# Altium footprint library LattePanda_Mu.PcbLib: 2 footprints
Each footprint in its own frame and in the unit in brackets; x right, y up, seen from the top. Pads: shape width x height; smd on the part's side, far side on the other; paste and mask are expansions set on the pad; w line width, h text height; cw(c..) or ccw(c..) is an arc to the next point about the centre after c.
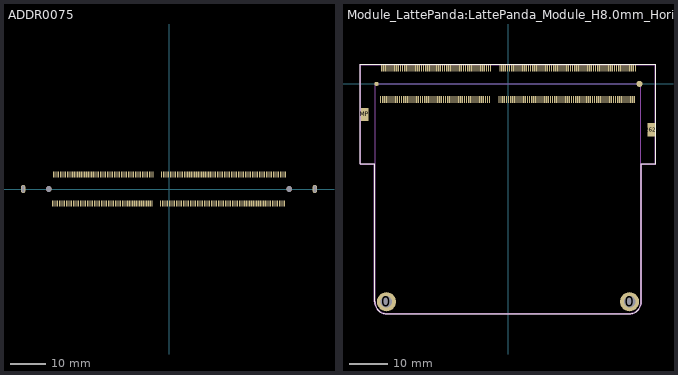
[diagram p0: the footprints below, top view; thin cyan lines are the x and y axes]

## ADDR0075 [mm]
pads (264):
  rect 0.3x1.75 smd paste+0 mask+0.05: 1(33.375,4.1) 2(33.125,-4.1) 3(32.875,4.1) 4(32.625,-4.1) 5(32.375,4.1) 6(32.125,-4.1) 7(31.875,4.1) 8(31.625,-4.1) 9(31.375,4.1) 10(31.125,-4.1) 11(30.875,4.1) 12(30.625,-4.1) 13(30.375,4.1) 14(30.125,-4.1) 15(29.875,4.1) 16(29.625,-4.1) 17(29.375,4.1) 18(29.125,-4.1) 19(28.875,4.1) 20(28.625,-4.1) 21(28.375,4.1) 22(28.125,-4.1) 23(27.875,4.1) 24(27.625,-4.1) 25(27.375,4.1) 26(27.125,-4.1) 27(26.875,4.1) 28(26.625,-4.1) 29(26.375,4.1) 30(26.125,-4.1) 31(25.875,4.1) 32(25.625,-4.1) 33(25.375,4.1) 34(25.125,-4.1) 35(24.875,4.1) 36(24.625,-4.1) 37(24.375,4.1) 38(24.125,-4.1) 39(23.875,4.1) 40(23.625,-4.1) 41(23.375,4.1) 42(23.125,-4.1) 43(22.875,4.1) 44(22.625,-4.1) 45(22.375,4.1) 46(22.125,-4.1) 47(21.875,4.1) 48(21.625,-4.1) 49(21.375,4.1) 50(21.125,-4.1) 51(20.875,4.1) 52(20.625,-4.1) 53(20.375,4.1) 54(20.125,-4.1) 55(19.875,4.1) 56(19.625,-4.1) 57(19.375,4.1) 58(19.125,-4.1) 59(18.875,4.1) 60(18.625,-4.1) 61(18.375,4.1) 62(18.125,-4.1) 63(17.875,4.1) 64(17.625,-4.1) 65(17.375,4.1) 66(17.125,-4.1) 67(16.875,4.1) 68(16.625,-4.1) 69(16.375,4.1) 70(16.125,-4.1) 71(15.875,4.1) 72(15.625,-4.1) 73(15.375,4.1) 74(15.125,-4.1) 75(14.875,4.1) 76(14.625,-4.1) 77(14.375,4.1) 78(14.125,-4.1) 79(13.875,4.1) 80(13.625,-4.1) 81(13.375,4.1) 82(13.125,-4.1) 83(12.875,4.1) 84(12.625,-4.1) 85(12.375,4.1) 86(12.125,-4.1) 87(11.875,4.1) 88(11.625,-4.1) 89(11.375,4.1) 90(11.125,-4.1) 91(10.875,4.1) 92(10.625,-4.1) 93(10.375,4.1) 94(10.125,-4.1) 95(9.875,4.1) 96(9.625,-4.1) 97(9.375,4.1) 98(9.125,-4.1) 99(8.875,4.1) 100(8.625,-4.1) 101(8.375,4.1) 102(8.125,-4.1) 103(7.875,4.1) 104(7.625,-4.1) 105(7.375,4.1) 106(7.125,-4.1) 107(6.875,4.1) 108(6.625,-4.1) 109(6.375,4.1) 110(6.125,-4.1) 111(5.875,4.1) 112(5.625,-4.1) 113(5.375,4.1) 114(5.125,-4.1) 115(4.875,4.1) 116(4.625,-4.1) 117(4.375,4.1) 118(4.125,-4.1) 119(3.875,4.1) 120(3.625,-4.1) 121(3.375,4.1) 122(3.125,-4.1) 123(2.875,4.1) 124(2.625,-4.1) 125(2.375,4.1) 126(2.125,-4.1) 127(1.875,4.1) 128(1.625,-4.1) 129(1.375,4.1) 130(1.125,-4.1) 131(0.875,4.1) 132(0.625,-4.1) 133(0.375,4.1) 134(0.125,-4.1) 135(-0.125,4.1) 136(-0.375,-4.1) 137(-0.625,4.1) 138(-0.875,-4.1) 139(-1.125,4.1) 140(-1.375,-4.1) 141(-1.625,4.1) 142(-1.875,-4.1) 143(-2.125,4.1) 144(-2.375,-4.1) 145(-4.625,4.1) 146(-4.875,-4.1) 147(-5.125,4.1) 148(-5.375,-4.1) 149(-5.625,4.1) 150(-5.875,-4.1) 151(-6.125,4.1) 152(-6.375,-4.1) 153(-6.625,4.1) 154(-6.875,-4.1) 155(-7.125,4.1) 156(-7.375,-4.1) 157(-7.625,4.1) 158(-7.875,-4.1) 159(-8.125,4.1) 160(-8.375,-4.1) 161(-8.625,4.1) 162(-8.875,-4.1) 163(-9.125,4.1) 164(-9.375,-4.1) 165(-9.625,4.1) 166(-9.875,-4.1) 167(-10.125,4.1) 168(-10.375,-4.1) 169(-10.625,4.1) 170(-10.875,-4.1) 171(-11.125,4.1) 172(-11.375,-4.1) 173(-11.625,4.1) 174(-11.875,-4.1) 175(-12.125,4.1) 176(-12.375,-4.1) 177(-12.625,4.1) 178(-12.875,-4.1) 179(-13.125,4.1) 180(-13.375,-4.1) 181(-13.625,4.1) 182(-13.875,-4.1) 183(-14.125,4.1) 184(-14.375,-4.1) 185(-14.625,4.1) 186(-14.875,-4.1) 187(-15.125,4.1) 188(-15.375,-4.1) 189(-15.625,4.1) 190(-15.875,-4.1) 191(-16.125,4.1) 192(-16.375,-4.1) 193(-16.625,4.1) 194(-16.875,-4.1) 195(-17.125,4.1) 196(-17.375,-4.1) 197(-17.625,4.1) 198(-17.875,-4.1) 199(-18.125,4.1) 200(-18.375,-4.1) 201(-18.625,4.1) 202(-18.875,-4.1) 203(-19.125,4.1) 204(-19.375,-4.1) 205(-19.625,4.1) 206(-19.875,-4.1) 207(-20.125,4.1) 208(-20.375,-4.1) 209(-20.625,4.1) 210(-20.875,-4.1) 211(-21.125,4.1) 212(-21.375,-4.1) 213(-21.625,4.1) 214(-21.875,-4.1) 215(-22.125,4.1) 216(-22.375,-4.1) 217(-22.625,4.1) 218(-22.875,-4.1) 219(-23.125,4.1) 220(-23.375,-4.1) 221(-23.625,4.1) 222(-23.875,-4.1) 223(-24.125,4.1) 224(-24.375,-4.1) 225(-24.625,4.1) 226(-24.875,-4.1) 227(-25.125,4.1) 228(-25.375,-4.1) 229(-25.625,4.1) 230(-25.875,-4.1) 231(-26.125,4.1) 232(-26.375,-4.1) 233(-26.625,4.1) 234(-26.875,-4.1) 235(-27.125,4.1) 236(-27.375,-4.1) 237(-27.625,4.1) 238(-27.875,-4.1) 239(-28.125,4.1) 240(-28.375,-4.1) 241(-28.625,4.1) 242(-28.875,-4.1) 243(-29.125,4.1) 244(-29.375,-4.1) 245(-29.625,4.1) 246(-29.875,-4.1) 247(-30.125,4.1) 248(-30.375,-4.1) 249(-30.625,4.1) 250(-30.875,-4.1) 251(-31.125,4.1) 252(-31.375,-4.1) 253(-31.625,4.1) 254(-31.875,-4.1) 255(-32.125,4.1) 256(-32.375,-4.1) 257(-32.625,4.1) 258(-32.875,-4.1) 259(-33.125,4.1) 260(-33.375,-4.1)
  oval 1.2x2.4 hole 0.7 slot 1.9 at 90 deg paste-2539.97: 261(-41.75,0) 261(41.75,0)
  round 1.6 hole 1.6 unplated paste-2539.97: 261(-34.4,0) 261(34.4,0)
3D body "2.STEP": height 28.6, standoff -1, extent -4.857,-42.499 80.443,-34.099

## Module_LattePanda:LattePanda_Module_H8.0mm_Horizontal [mm]
pads (266):
  round 5 hole 3 mask+0.05: 0(-31.8,-57) 0(31.8,-57)
  rect 0.3x1.75 smd paste+0: 1(33.375,4.1) 2(33.125,-4.1) 3(32.875,4.1) 4(32.625,-4.1) 5(32.375,4.1) 6(32.125,-4.1) 7(31.875,4.1) 8(31.625,-4.1) 9(31.375,4.1) 10(31.125,-4.1) 11(30.875,4.1) 12(30.625,-4.1) 13(30.375,4.1) 14(30.125,-4.1) 15(29.875,4.1) 16(29.625,-4.1) 17(29.375,4.1) 18(29.125,-4.1) 19(28.875,4.1) 20(28.625,-4.1) 21(28.375,4.1) 22(28.125,-4.1) 23(27.875,4.1) 24(27.625,-4.1) 25(27.375,4.1) 26(27.125,-4.1) 27(26.875,4.1) 28(26.625,-4.1) 29(26.375,4.1) 30(26.125,-4.1) 31(25.875,4.1) 32(25.625,-4.1) 33(25.375,4.1) 34(25.125,-4.1) 35(24.875,4.1) 36(24.625,-4.1) 37(24.375,4.1) 38(24.125,-4.1) 39(23.875,4.1) 40(23.625,-4.1) 41(23.375,4.1) 42(23.125,-4.1) 43(22.875,4.1) 44(22.625,-4.1) 45(22.375,4.1) 46(22.125,-4.1) 47(21.875,4.1) 48(21.625,-4.1) 49(21.375,4.1) 50(21.125,-4.1) 51(20.875,4.1) 52(20.625,-4.1) 53(20.375,4.1) 54(20.125,-4.1) 55(19.875,4.1) 56(19.625,-4.1) 57(19.375,4.1) 58(19.125,-4.1) 59(18.875,4.1) 60(18.625,-4.1) 61(18.375,4.1) 62(18.125,-4.1) 63(17.875,4.1) 64(17.625,-4.1) 65(17.375,4.1) 66(17.125,-4.1) 67(16.875,4.1) 68(16.625,-4.1) 69(16.375,4.1) 70(16.125,-4.1) 71(15.875,4.1) 72(15.625,-4.1) 73(15.375,4.1) 74(15.125,-4.1) 75(14.875,4.1) 76(14.625,-4.1) 77(14.375,4.1) 78(14.125,-4.1) 79(13.875,4.1) 80(13.625,-4.1) 81(13.375,4.1) 82(13.125,-4.1) 83(12.875,4.1) 84(12.625,-4.1) 85(12.375,4.1) 86(12.125,-4.1) 87(11.875,4.1) 88(11.625,-4.1) 89(11.375,4.1) 90(11.125,-4.1) 91(10.875,4.1) 92(10.625,-4.1) 93(10.375,4.1) 94(10.125,-4.1) 95(9.875,4.1) 96(9.625,-4.1) 97(9.375,4.1) 98(9.125,-4.1) 99(8.875,4.1) 100(8.625,-4.1) 101(8.375,4.1) 102(8.125,-4.1) 103(7.875,4.1) 104(7.625,-4.1) 105(7.375,4.1) 106(7.125,-4.1) 107(6.875,4.1) 108(6.625,-4.1) 109(6.375,4.1) 110(6.125,-4.1) 111(5.875,4.1) 112(5.625,-4.1) 113(5.375,4.1) 114(5.125,-4.1) 115(4.875,4.1) 116(4.625,-4.1) 117(4.375,4.1) 118(4.125,-4.1) 119(3.875,4.1) 120(3.625,-4.1) 121(3.375,4.1) 122(3.125,-4.1) 123(2.875,4.1) 124(2.625,-4.1) 125(2.375,4.1) 126(2.125,-4.1) 127(1.875,4.1) 128(1.625,-4.1) 129(1.375,4.1) 130(1.125,-4.1) 131(0.875,4.1) 132(0.625,-4.1) 133(0.375,4.1) 134(0.125,-4.1) 135(-0.125,4.1) 136(-0.375,-4.1) 137(-0.625,4.1) 138(-0.875,-4.1) 139(-1.125,4.1) 140(-1.375,-4.1) 141(-1.625,4.1) 142(-1.875,-4.1) 143(-2.125,4.1) 144(-2.375,-4.1) 145(-4.625,4.1) 146(-4.875,-4.1) 147(-5.125,4.1) 148(-5.375,-4.1) 149(-5.625,4.1) 150(-5.875,-4.1) 151(-6.125,4.1) 152(-6.375,-4.1) 153(-6.625,4.1) 154(-6.875,-4.1) 155(-7.125,4.1) 156(-7.375,-4.1) 157(-7.625,4.1) 158(-7.875,-4.1) 159(-8.125,4.1) 160(-8.375,-4.1) 161(-8.625,4.1) 162(-8.875,-4.1) 163(-9.125,4.1) 164(-9.375,-4.1) 165(-9.625,4.1) 166(-9.875,-4.1) 167(-10.125,4.1) 168(-10.375,-4.1) 169(-10.625,4.1) 170(-10.875,-4.1) 171(-11.125,4.1) 172(-11.375,-4.1) 173(-11.625,4.1) 174(-11.875,-4.1) 175(-12.125,4.1) 176(-12.375,-4.1) 177(-12.625,4.1) 178(-12.875,-4.1) 179(-13.125,4.1) 180(-13.375,-4.1) 181(-13.625,4.1) 182(-13.875,-4.1) 183(-14.125,4.1) 184(-14.375,-4.1) 185(-14.625,4.1) 186(-14.875,-4.1) 187(-15.125,4.1) 188(-15.375,-4.1) 189(-15.625,4.1) 190(-15.875,-4.1) 191(-16.125,4.1) 192(-16.375,-4.1) 193(-16.625,4.1) 194(-16.875,-4.1) 195(-17.125,4.1) 196(-17.375,-4.1) 197(-17.625,4.1) 198(-17.875,-4.1) 199(-18.125,4.1) 200(-18.375,-4.1) 201(-18.625,4.1) 202(-18.875,-4.1) 203(-19.125,4.1) 204(-19.375,-4.1) 205(-19.625,4.1) 206(-19.875,-4.1) 207(-20.125,4.1) 208(-20.375,-4.1) 209(-20.625,4.1) 210(-20.875,-4.1) 211(-21.125,4.1) 212(-21.375,-4.1) 213(-21.625,4.1) 214(-21.875,-4.1) 215(-22.125,4.1) 216(-22.375,-4.1) 217(-22.625,4.1) 218(-22.875,-4.1) 219(-23.125,4.1) 220(-23.375,-4.1) 221(-23.625,4.1) 222(-23.875,-4.1) 223(-24.125,4.1) 224(-24.375,-4.1) 225(-24.625,4.1) 226(-24.875,-4.1) 227(-25.125,4.1) 228(-25.375,-4.1) 229(-25.625,4.1) 230(-25.875,-4.1) 231(-26.125,4.1) 232(-26.375,-4.1) 233(-26.625,4.1) 234(-26.875,-4.1) 235(-27.125,4.1) 236(-27.375,-4.1) 237(-27.625,4.1) 238(-27.875,-4.1) 239(-28.125,4.1) 240(-28.375,-4.1) 241(-28.625,4.1) 242(-28.875,-4.1) 243(-29.125,4.1) 244(-29.375,-4.1) 245(-29.625,4.1) 246(-29.875,-4.1) 247(-30.125,4.1) 248(-30.375,-4.1) 249(-30.625,4.1) 250(-30.875,-4.1) 251(-31.125,4.1) 252(-31.375,-4.1) 253(-31.625,4.1) 254(-31.875,-4.1) 255(-32.125,4.1) 256(-32.375,-4.1) 257(-32.625,4.1) 258(-32.875,-4.1) 259(-33.125,4.1) 260(-33.375,-4.1)
  round 1.6 smd paste+0: 261(34.4,0)
  rect 2x3.5 smd paste+0: 262(37.5,-12) MP(-37.5,-8)
  round 1.1 smd paste+0: 263(-34.4,0)
Top Overlay:
  lines w0.254: -38.6,-20.95 -38.6,5.1 38.6,5.1 38.6,-20.95 34.9,-20.95 34.9,-57 cw(c31.8,-57) 31.8,-60.1 -31.8,-60.1 cw(c-31.8,-57) -34.9,-57 -34.9,-20.95 -38.6,-20.95
Mechanical 6:
  lines w0.254: -38.7,-21.05 -38.7,5.2 38.7,5.2 38.7,-21.05 35,-21.05 35,-57 cw(c31.8,-57) 31.8,-60.2 -31.8,-60.2 cw(c-31.8,-57) -35,-57 -35,-21.05 -38.7,-21.05
Mechanical 15:
  circle w0.025: c-31.8,-57 r1.1
  circle w0.025: c-31.8,-57 r2
  circle w0.025: c31.8,-57 r1.1
  circle w0.025: c31.8,-57 r2
  lines w0.254: -34.8,-20.85 -38.5,-20.85 -38.5,5 38.5,5 38.5,-20.85 34.8,-20.85 ; -34.8,-57 ccw(c-31.8,-57) -31.8,-60 31.8,-60 ccw(c31.8,-57) 34.8,-57 34.8,0 -34.8,0 -34.8,-57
